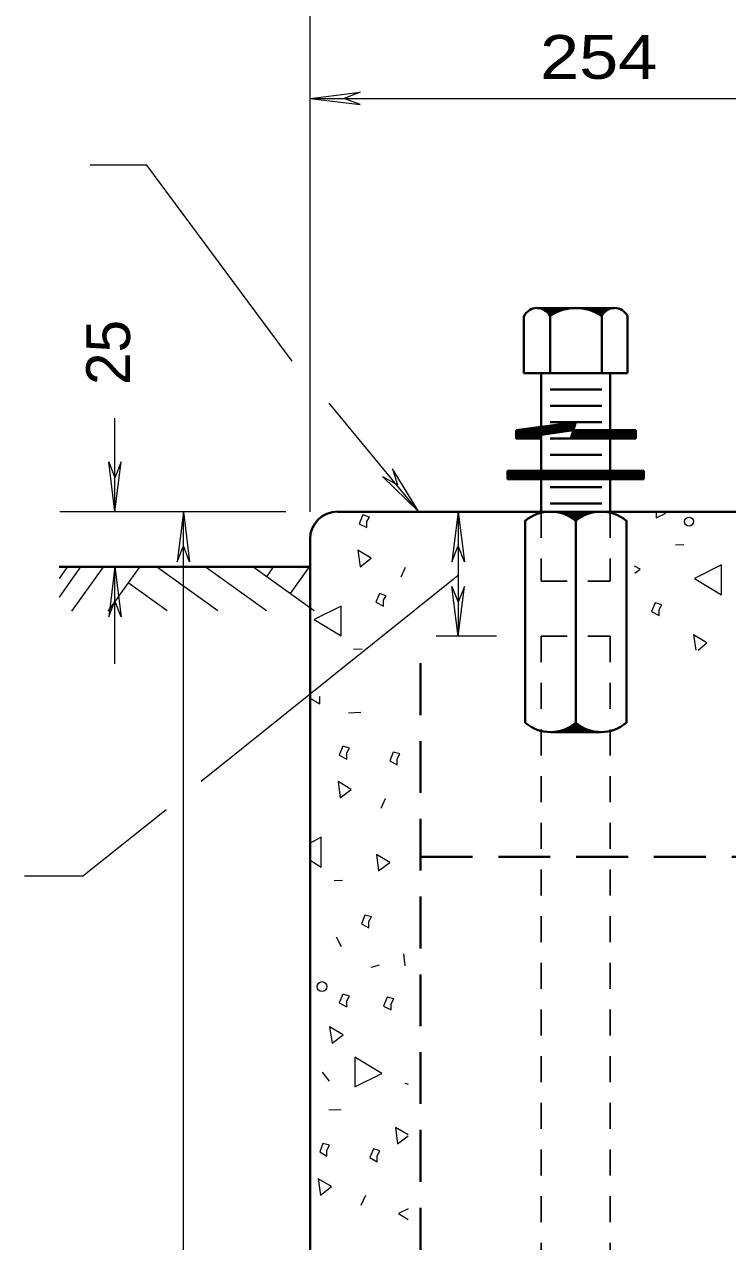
# Model space of a CAD drawing. Extents: x 312583 to 312854, y 144419 to 144597.
# Drawn here: x 312692.43 to 312704.63, y 144459.67 to 144480.8 of the extents above; entities that cross this region are included whole.
import ezdxf

# ---------------------------------------------------------------- set-up
doc = ezdxf.new("R2010")
doc.units = 0
doc.header["$LTSCALE"] = 0.3
doc.linetypes.add('MEDIUM_DASHED', pattern=[4.5, 3, -1.5])
doc.linetypes.add('SHORT_DASHED', pattern=[2.7, 1.5, -1.2])
doc.layers.add('1', color=7, linetype='Continuous', lineweight=13)

msp = doc.modelspace()

# ---------------------------------------------------------------- linework, layer by layer
at = {"layer": '1'}
for p, q in [((312697.3886, 144472.3419), (312697.3886, 144483.6272)), ((312697.3886, 144479.5179), (312698.2549, 144479.6252)), ((312697.3886, 144479.5179), (312698.2549, 144479.4105)), ((312698.2549, 144479.6252), (312697.9789, 144479.5179)), ((312698.2549, 144479.4105), (312697.9789, 144479.5179)), ((312694.5519, 144478.3602), (312693.5706, 144478.3602)), ((312697.0743, 144474.9562), (312694.5519, 144478.3602)), ((312699.2746, 144472.3419), (312697.7183, 144474.2279)), ((312693.9999, 144472.3419), (312693.9999, 144473.9672)), ((312693.8926, 144473.2082), (312693.9999, 144472.9322)), ((312693.9999, 144472.3419), (312693.8926, 144473.2082)), ((312694.1073, 144473.2082), (312693.9999, 144472.9322)), ((312693.9999, 144472.3419), (312694.1073, 144473.2082)), ((312698.6459, 144472.9552), (312698.9066, 144472.8095)), ((312699.2746, 144472.3419), (312698.6459, 144472.9552)), ((312698.8146, 144473.0855), (312698.9066, 144472.8095)), ((312699.2746, 144472.3419), (312698.8146, 144473.0855)), ((312696.9669, 144472.3419), (312693.0416, 144472.3419)), ((312695.1883, 144472.3419), (312695.0809, 144471.4755)), ((312695.1883, 144472.3419), (312695.2956, 144471.4755)), ((312695.1883, 144429.2169), (312695.1883, 144472.3419)), ((312699.9569, 144472.3419), (312699.8496, 144471.4755)), ((312699.9569, 144472.3419), (312699.9569, 144470.1799)), ((312699.9569, 144472.3419), (312700.0643, 144471.4755)), ((312695.0809, 144471.4755), (312695.1883, 144471.7515)), ((312695.2956, 144471.4755), (312695.1883, 144471.7515)), ((312699.8496, 144471.4755), (312699.9569, 144471.7515)), ((312700.0643, 144471.4755), (312699.9569, 144471.7515)), ((312703.7289, 144471.7669), (312703.8746, 144471.7745)), ((312693.4019, 144471.3835), (312693.0339, 144470.8622)), ((312693.1643, 144471.3759), (312693.0339, 144471.1842)), ((312693.7929, 144471.3759), (312693.2486, 144470.6169)), ((312694.4216, 144471.3759), (312693.8773, 144470.6169)), ((312693.9999, 144471.3835), (312693.8926, 144470.5172)), ((312693.9999, 144469.7045), (312693.9999, 144471.3835)), ((312693.9999, 144471.3835), (312694.1073, 144470.5172)), ((312695.7863, 144470.6245), (312694.7206, 144471.3835)), ((312699.9569, 144471.2379), (312695.4949, 144467.6575)), ((312696.6296, 144470.6245), (312695.5869, 144471.3682)), ((312697.4576, 144470.6245), (312696.3919, 144471.3835)), ((312696.7446, 144471.3835), (312696.6296, 144471.2149)), ((312697.3733, 144471.3835), (312697.0436, 144470.9235)), ((312699.0369, 144471.3759), (312698.9603, 144471.2072)), ((312694.9046, 144470.6245), (312694.2299, 144471.1075)), ((312699.8496, 144471.0462), (312699.9569, 144470.7702)), ((312699.9569, 144470.1799), (312699.8496, 144471.0462)), ((312700.0643, 144471.0462), (312699.9569, 144470.7702)), ((312699.9569, 144470.1799), (312700.0643, 144471.0462)), ((312693.8926, 144470.5172), (312693.9999, 144470.7932)), ((312694.1073, 144470.5172), (312693.9999, 144470.7932)), ((312700.6239, 144470.1799), (312699.5736, 144470.1799)), ((312698.1399, 144469.9575), (312698.2933, 144469.9652)), ((312697.3886, 144469.1065), (312697.5573, 144469.0069)), ((312697.5573, 144469.0069), (312697.5573, 144469.1372)), ((312698.0556, 144468.8535), (312698.2703, 144468.8612)), ((312698.6919, 144467.3585), (312698.6153, 144467.1899)), ((312693.4403, 144466.0169), (312694.8893, 144467.1745)), ((312697.3886, 144466.2929), (312697.5803, 144466.1702)), ((312693.4403, 144466.0169), (312692.4283, 144466.0169)), ((312697.8026, 144465.9402), (312697.9483, 144465.9479)), ((312697.8409, 144464.9665), (312697.9253, 144464.7979)), ((312699.0063, 144464.6675), (312699.0293, 144464.4605)), ((312698.4466, 144464.4375), (312698.5923, 144464.4759)), ((312697.5956, 144462.6129), (312697.7183, 144462.4595)), ((312699.0293, 144462.4212), (312699.0906, 144462.4059)), ((312697.7106, 144461.9612), (312697.9253, 144461.9689)), ((312698.9066, 144461.3709), (312699.0906, 144461.5089)), ((312698.3469, 144460.4739), (312698.2703, 144460.2975))]:
    msp.add_line(p, q, dxfattribs=at)
at = {"layer": '1', "lineweight": 40}
for p, q in [((312701.3293, 144475.8762), (312702.6709, 144475.8762)), ((312701.0993, 144475.7382), (312701.0993, 144474.7492)), ((312701.5516, 144475.7382), (312701.5516, 144474.7492)), ((312702.4486, 144475.7382), (312702.4486, 144474.7492)), ((312702.8933, 144475.7382), (312702.8933, 144474.7492)), ((312701.0993, 144474.7492), (312702.8933, 144474.7492)), ((312701.3983, 144474.7492), (312701.3983, 144472.3419)), ((312702.5943, 144474.7492), (312702.5943, 144472.3419)), ((312701.5516, 144474.4655), (312702.4486, 144474.4655)), ((312701.5516, 144474.1819), (312702.4486, 144474.1819)), ((312700.9613, 144473.7602), (312700.9613, 144473.6145)), ((312701.5516, 144473.8982), (312702.4486, 144473.8982)), ((312701.9579, 144473.7602), (312703.0389, 144473.7602)), ((312703.0389, 144473.7602), (312703.0389, 144473.6145)), ((312701.5516, 144473.6145), (312702.4486, 144473.6145)), ((312701.9119, 144473.6145), (312703.0389, 144473.6145)), ((312701.5516, 144473.3309), (312702.4486, 144473.3309)), ((312700.8156, 144473.0549), (312703.1769, 144473.0549)), ((312700.8156, 144473.0549), (312700.8156, 144472.9092)), ((312700.8156, 144473.0165), (312703.1769, 144473.0165)), ((312700.8156, 144472.9782), (312703.1769, 144472.9782)), ((312700.8156, 144472.9399), (312703.1769, 144472.9399)), ((312700.8156, 144472.9092), (312703.1769, 144472.9092)), ((312703.1769, 144473.0549), (312703.1769, 144472.9092)), ((312701.5516, 144472.7712), (312702.4486, 144472.7712)), ((312701.5516, 144472.4875), (312702.4486, 144472.4875)), ((312697.8639, 144472.3419), (312716.0723, 144472.3419)), ((312701.3983, 144472.3419), (312702.5943, 144472.3419)), ((312701.5593, 144472.3419), (312702.4333, 144472.3419)), ((312701.9963, 144472.3419), (312701.9963, 144468.5162)), ((312701.1223, 144472.1885), (312701.1223, 144468.6772)), ((312702.8779, 144472.1885), (312702.8779, 144468.6772)), ((312697.3886, 144471.8665), (312697.3886, 144469.7122)), ((312697.3886, 144471.3835), (312693.0339, 144471.3835)), ((312697.3886, 144469.7122), (312697.3886, 144429.2169)), ((312701.5593, 144468.5162), (312702.4333, 144468.5162))]:
    msp.add_line(p, q, dxfattribs=at)
at = {"layer": '1', "linetype": 'SHORT_DASHED', "lineweight": 25}
for p, q in [((312701.3983, 144472.3419), (312701.3983, 144471.1382)), ((312702.5943, 144472.3419), (312702.5943, 144471.1382)), ((312701.3983, 144471.1382), (312702.5943, 144471.1382)), ((312701.3983, 144470.1799), (312702.5943, 144470.1799)), ((312701.3983, 144470.1799), (312701.3983, 144437.9569)), ((312702.5943, 144470.1799), (312702.5943, 144437.9569))]:
    msp.add_line(p, q, dxfattribs=at)
at = {"layer": '1', "linetype": 'MEDIUM_DASHED', "lineweight": 40}
for p, q in [((312699.3053, 144469.7122), (312699.3053, 144432.0919)), ((312699.3053, 144466.3542), (312738.8346, 144466.3542))]:
    msp.add_line(p, q, dxfattribs=at)
at = {"layer": '1'}
for points in [[(312697.3886, 144479.5179), (312706.9719, 144479.5179), (312716.5553, 144479.5179)], [(312703.3916, 144472.3189), (312703.3916, 144472.2345), (312703.5603, 144472.3189)], [(312703.0236, 144471.2762), (312703.1156, 144471.3452), (312703.0159, 144471.3989)], [(312704.1199, 144469.9422), (312704.2733, 144470.0649), (312704.0433, 144470.2029), (312704.0816, 144469.9422)], [(312697.5803, 144466.1702), (312697.5803, 144466.6915), (312697.3886, 144466.5919)], [(312699.0906, 144461.5242), (312698.8683, 144461.6545), (312698.9066, 144461.3709)], [(312699.0906, 144460.2439), (312698.9219, 144460.1595), (312699.0906, 144460.0599)]]:
    msp.add_lwpolyline(points, dxfattribs=at)
at = {"layer": '1', "lineweight": 40}
for points in [[(312701.3829, 144475.8762), (312701.8813, 144475.8762), (312701.7969, 144475.8609), (312701.7433, 144475.8455), (312701.6513, 144475.8072), (312701.5516, 144475.7459), (312701.5209, 144475.7995), (312701.4749, 144475.8302), (312701.4059, 144475.8685), (312701.8429, 144475.8685), (312701.7203, 144475.8455), (312701.6283, 144475.7995), (312701.5593, 144475.7612), (312701.4826, 144475.8302), (312701.4366, 144475.8609), (312701.7893, 144475.8685), (312701.6666, 144475.8302), (312701.5593, 144475.7689), (312701.4596, 144475.8532), (312701.7509, 144475.8609), (312701.5516, 144475.7842), (312701.4749, 144475.8532), (312701.7203, 144475.8532), (312701.5439, 144475.7919), (312701.4979, 144475.8455), (312701.6819, 144475.8532), (312701.5516, 144475.8072), (312701.5133, 144475.8379), (312701.6359, 144475.8379), (312701.5593, 144475.8149), (312701.5363, 144475.8379), (312701.5899, 144475.8302), (312701.5593, 144475.8225)], [(312702.6173, 144475.8762), (312702.1113, 144475.8762), (312702.1956, 144475.8609), (312702.2569, 144475.8455), (312702.3489, 144475.8072), (312702.4486, 144475.7459), (312702.4793, 144475.7995), (312702.5176, 144475.8302), (312702.5943, 144475.8685), (312702.1573, 144475.8685), (312702.2799, 144475.8455), (312702.3719, 144475.7995), (312702.4409, 144475.7612), (312702.5099, 144475.8302), (312702.5636, 144475.8609), (312702.2109, 144475.8685), (312702.3336, 144475.8302), (312702.4409, 144475.7689), (312702.5406, 144475.8532), (312702.2493, 144475.8609), (312702.4486, 144475.7842), (312702.5253, 144475.8532), (312702.2799, 144475.8532), (312702.4486, 144475.7919), (312702.5023, 144475.8455), (312702.3183, 144475.8532), (312702.4486, 144475.8072), (312702.4793, 144475.8379), (312702.3643, 144475.8379), (312702.4409, 144475.8149), (312702.4563, 144475.8379), (312702.4103, 144475.8302), (312702.4409, 144475.8225)], [(312700.9613, 144473.7602), (312701.9963, 144473.8982), (312701.9119, 144473.6145)], [(312701.9579, 144473.7602), (312700.9613, 144473.6145), (312701.3983, 144473.6145)], [(312701.3983, 144473.6145), (312700.9689, 144473.6375), (312700.9766, 144473.7449), (312701.9733, 144473.8752), (312701.9349, 144473.7755), (312701.3906, 144473.6912), (312701.3829, 144473.6375), (312700.9843, 144473.6529), (312700.9919, 144473.7295), (312701.9503, 144473.8599), (312701.9196, 144473.7832), (312701.3676, 144473.6989), (312701.3599, 144473.6529), (312700.9996, 144473.6682), (312700.9996, 144473.7065), (312701.9043, 144473.8369), (312701.9119, 144473.8062), (312701.3753, 144473.7142), (312701.3446, 144473.6989), (312701.2296, 144473.6682), (312701.0226, 144473.6835), (312701.8813, 144473.8215), (312701.1606, 144473.6835)], [(312701.9349, 144473.6375), (312703.0159, 144473.6375), (312703.0159, 144473.7449), (312701.9733, 144473.7372), (312701.9349, 144473.6529), (312703.0006, 144473.6452), (312703.0006, 144473.7219), (312701.9886, 144473.7142), (312701.9656, 144473.6682), (312702.9776, 144473.6759), (312702.9623, 144473.6989), (312702.9623, 144473.7065), (312701.9963, 144473.6989), (312701.9809, 144473.6835), (312702.9546, 144473.6835)], [(312701.6743, 144472.3419), (312702.3259, 144472.3419), (312702.2493, 144472.3265), (312702.1803, 144472.3035), (312702.1113, 144472.2729), (312702.0653, 144472.2499), (312702.0039, 144472.2039), (312701.9963, 144472.1962), (312701.8813, 144472.2805), (312701.7739, 144472.3189), (312701.7049, 144472.3342), (312702.2799, 144472.3342), (312702.2339, 144472.3265), (312702.1803, 144472.3189), (312702.1113, 144472.2959), (312702.0423, 144472.2575), (312702.0193, 144472.2345), (312701.9963, 144472.2115), (312701.8889, 144472.2805), (312701.7739, 144472.3265), (312702.1956, 144472.3265), (312702.0959, 144472.2959), (312701.9963, 144472.2345), (312701.8123, 144472.3189), (312702.1496, 144472.3265), (312701.9963, 144472.2269), (312701.8506, 144472.3112), (312702.1189, 144472.3189), (312702.0039, 144472.2499), (312701.9043, 144472.3035), (312702.0806, 144472.3035), (312701.9963, 144472.2805), (312701.9043, 144472.2959), (312701.9656, 144472.2575), (312701.9809, 144472.3035), (312701.9886, 144472.2422), (312702.0346, 144472.2882), (312702.0576, 144472.2882), (312702.0883, 144472.3035)], [(312701.6743, 144468.5239), (312702.3259, 144468.5239), (312702.2493, 144468.5392), (312702.1803, 144468.5545), (312702.1113, 144468.5852), (312702.0653, 144468.6159), (312702.0039, 144468.6542), (312701.9963, 144468.6619), (312701.8813, 144468.5852), (312701.7739, 144468.5469), (312701.7049, 144468.5315), (312702.2799, 144468.5239), (312702.2339, 144468.5315), (312702.1803, 144468.5469), (312702.1113, 144468.5699), (312702.0423, 144468.6082), (312702.0193, 144468.6312), (312701.9963, 144468.6542), (312701.8889, 144468.5775), (312701.7739, 144468.5392), (312702.1956, 144468.5315), (312702.0959, 144468.5699), (312701.9963, 144468.6312), (312701.8123, 144468.5392), (312702.1496, 144468.5392), (312701.9963, 144468.6389), (312701.8506, 144468.5469), (312702.1189, 144468.5469), (312702.0039, 144468.6082), (312701.9043, 144468.5622), (312702.0806, 144468.5545), (312701.9963, 144468.5852), (312701.9043, 144468.5699), (312701.9656, 144468.6005), (312701.9809, 144468.5622), (312701.9886, 144468.6235), (312702.0346, 144468.5775), (312702.0576, 144468.5699), (312702.0883, 144468.5622)]]:
    msp.add_lwpolyline(points, dxfattribs=at)
at = {"layer": '1'}
for points in [[(312698.3699, 144472.1732), (312698.4159, 144472.2499), (312698.3009, 144472.2882), (312698.2396, 144472.1349), (312698.3699, 144472.0659)], [(312698.2549, 144471.3835), (312698.4466, 144471.5369), (312698.2166, 144471.6749)], [(312704.5263, 144470.9005), (312704.5263, 144471.4219), (312704.0586, 144471.1842)], [(312698.6613, 144470.8085), (312698.7073, 144470.8852), (312698.5923, 144470.9235), (312698.5309, 144470.7702), (312698.6613, 144470.7012)], [(312697.9253, 144470.1875), (312697.9253, 144470.7012), (312697.4576, 144470.4712)], [(312703.4453, 144470.6475), (312703.4913, 144470.7242), (312703.3763, 144470.7625), (312703.3149, 144470.6092), (312703.4453, 144470.5402)], [(312698.0249, 144468.1559), (312698.0709, 144468.2402), (312697.9559, 144468.2709), (312697.8946, 144468.1175), (312698.0249, 144468.0485)], [(312698.8989, 144468.0562), (312698.9449, 144468.1405), (312698.8299, 144468.1712), (312698.7686, 144468.0179), (312698.8989, 144467.9489)], [(312697.9099, 144467.3739), (312698.1016, 144467.5195), (312697.8716, 144467.6575)], [(312698.5769, 144466.1089), (312698.7686, 144466.2545), (312698.5386, 144466.3925)], [(312698.4083, 144465.2272), (312698.4543, 144465.3115), (312698.3393, 144465.3422), (312698.2779, 144465.1889), (312698.4083, 144465.1199)], [(312698.0249, 144463.8549), (312698.0709, 144463.9315), (312697.9559, 144463.9699), (312697.8946, 144463.8165), (312698.0249, 144463.7475)], [(312698.7916, 144463.8012), (312698.8376, 144463.8855), (312698.7226, 144463.9162), (312698.6613, 144463.7629), (312698.7916, 144463.6939)], [(312697.7719, 144463.1189), (312697.9636, 144463.2645), (312697.7259, 144463.4025)], [(312698.1629, 144462.8735), (312698.1629, 144462.3599), (312698.6306, 144462.5899)], [(312697.6799, 144461.2635), (312697.7259, 144461.3479), (312697.6109, 144461.3785), (312697.5573, 144461.2329), (312697.6799, 144461.1562)], [(312698.5539, 144461.1639), (312698.5999, 144461.2482), (312698.4849, 144461.2865), (312698.4236, 144461.1332), (312698.5539, 144461.0565)], [(312697.5649, 144460.4815), (312697.7566, 144460.6272), (312697.5266, 144460.7652)]]:
    msp.add_lwpolyline(points, close=True, dxfattribs=at)
for centre, radius in [((312703.9649, 144472.1722), 0.0784), ((312697.5939, 144464.0991), 0.0865)]:
    msp.add_circle(centre, radius, dxfattribs=at)
at = {"layer": '1', "lineweight": 40}
for centre, radius, start, end in [((312701.3248, 144475.6305), 0.2489, 25.60064, 154.39936), ((312701.9982, 144475.0958), 0.7836, 55.04559, 124.95441), ((312702.6716, 144475.6305), 0.2489, 25.60064, 154.39936), ((312697.8659, 144471.8665), 0.4792, 90, 180), ((312701.56, 144471.6636), 0.6817, 50.00693, 129.99306), ((312702.4363, 144471.6636), 0.6817, 50.00694, 129.99307), ((312701.56, 144469.2005), 0.6817, 230.00694, 309.99307), ((312702.4363, 144469.2005), 0.6817, 230.00693, 309.99306)]:
    msp.add_arc(centre, radius, start, end, dxfattribs=at)

# ---------------------------------------------------------------- texts
at = {"layer": '1', "width": 1.2}
msp.add_text('254 ', height=0.76, dxfattribs=at).set_placement((312701.3779, 144479.8565))
at = {"layer": '1'}
msp.add_text('25', height=0.76, rotation=90, dxfattribs=at).set_placement((312694.2623, 144474.5413))

doc.saveas('drawing.dxf')
